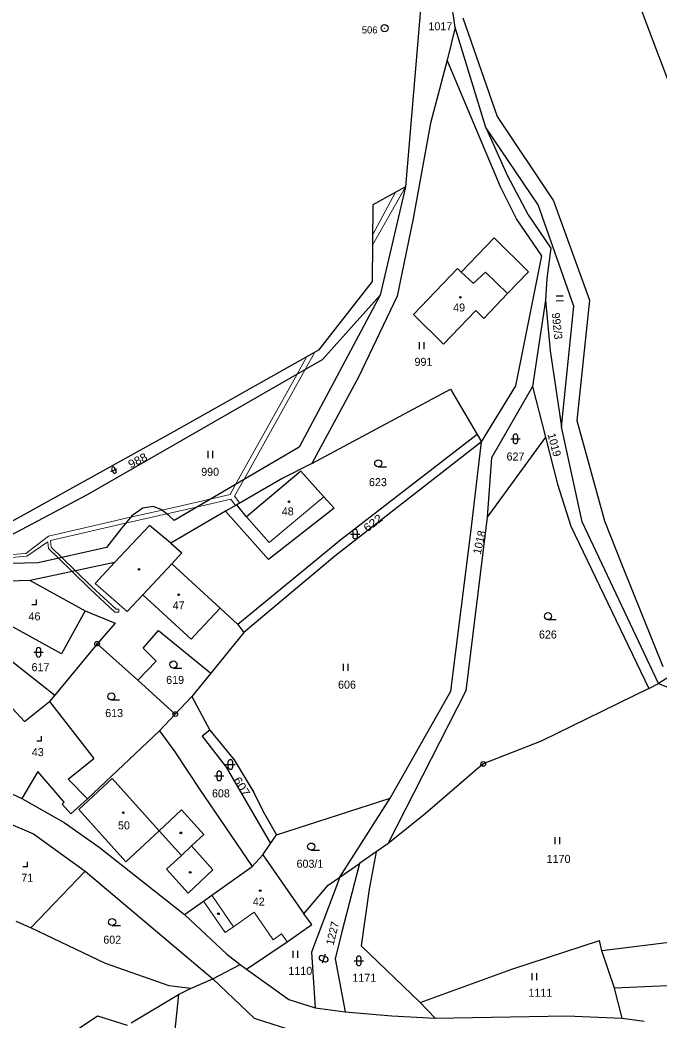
# Model space of a CAD drawing. Extents: x -744132 to -742433, y -984679 to -982287.
# Drawn here: x -742956.9 to -742821.1, y -983409.8 to -983197.5 of the extents above; entities that cross this region are included whole.
import ezdxf
from ezdxf.enums import TextEntityAlignment as Align

# ---------------------------------------------------------------- set-up
doc = ezdxf.new("R2010")
doc.units = 0
doc.header["$LTSCALE"] = 0.68
for name, color, linetype, lineweight in [('1', 7, 'Continuous', 25), ('13', 7, 'Continuous', 13), ('3', 7, 'Continuous', 25), ('4', 7, 'Continuous', 13), ('5', 7, 'Continuous', 25), ('8', 7, 'Continuous', 25)]:
    doc.layers.add(name, color=color, linetype=linetype, lineweight=lineweight)
doc.layers.add('2', color=7, linetype='Continuous')

msp = doc.modelspace()

# ---------------------------------------------------------------- linework, layer by layer
at = {"layer": '1'}
for p, q in [((-742864.59, -983199.1), (-742873.51, -983136.56)), ((-742821.79, -983203.81), (-742833.08, -983174.04)), ((-742871.62, -983191.87), (-742875.11, -983232.95)), ((-742862.92, -983197.05), (-742855.66, -983218)), ((-742864.59, -983199.1), (-742866.29, -983206.07)), ((-742858.03, -983220.3), (-742864.59, -983199.1)), ((-742797.61, -983268.25), (-742821.79, -983203.81)), ((-742866.29, -983206.07), (-742869.83, -983219.44)), ((-742854.97, -983232.92), (-742866.29, -983206.07)), ((-742855.66, -983218), (-742843.71, -983235.9)), ((-742869.83, -983219.44), (-742873.48, -983239.66)), ((-742858.03, -983220.3), (-742853.5, -983230.47)), ((-742846.95, -983236.77), (-742858.03, -983220.3)), ((-742853.5, -983230.47), (-742849.07, -983238.88)), ((-742875.11, -983232.95), (-742882.07, -983236.74)), ((-742875.11, -983232.95), (-742880.5, -983255.92)), ((-742851.57, -983239.74), (-742854.97, -983232.92)), ((-742882.07, -983236.74), (-742882.16, -983253.04)), ((-742839.35, -983258.24), (-742846.95, -983236.77)), ((-742843.71, -983235.9), (-742836.08, -983256.99)), ((-742873.48, -983239.66), (-742876.9, -983256.12)), ((-742846.16, -983247.57), (-742851.57, -983239.74)), ((-742849.07, -983238.88), (-742844.26, -983245.92)), ((-742856.29, -983243.76), (-742863.3, -983251.05)), ((-742856.29, -983243.76), (-742849.01, -983250.99)), ((-742844.26, -983245.92), (-742845.09, -983252.4)), ((-742851.67, -983275.18), (-742846.16, -983247.57)), ((-742864.08, -983250.28), (-742873.44, -983260.01)), ((-742864.08, -983250.28), (-742863.3, -983251.05)), ((-742849.01, -983250.99), (-742853.44, -983255.6)), ((-742845.09, -983252.4), (-742845.36, -983257.03)), ((-742882.16, -983253.04), (-742893.59, -983267.58)), ((-742880.5, -983255.92), (-742897.7, -983288.23)), ((-742892.71, -983269.57), (-742880.5, -983255.92)), ((-742876.9, -983256.12), (-742885.11, -983273.37)), ((-742853.44, -983255.6), (-742858.51, -983260.87)), ((-742845.36, -983257.03), (-742848.15, -983275.34)), ((-742845.36, -983257.03), (-742844.39, -983267.78)), ((-742842.01, -983283.87), (-742839.35, -983258.24)), ((-742836.08, -983256.99), (-742838.74, -983282.57)), ((-742873.44, -983260.01), (-742867.05, -983266.34)), ((-742860.19, -983259.21), (-742867.05, -983266.34)), ((-742860.19, -983259.21), (-742858.51, -983260.87)), ((-742893.59, -983267.58), (-742924.36, -983284.96)), ((-742844.39, -983267.78), (-742842.01, -983283.87)), ((-742942.64, -983298.23), (-742892.71, -983269.57)), ((-742885.11, -983273.37), (-742894.98, -983291.66)), ((-742858.98, -983287.1), (-742851.67, -983275.18)), ((-742848.15, -983275.34), (-742856.88, -983290.48)), ((-742848.15, -983275.34), (-742845.38, -983286.09)), ((-742894.98, -983291.66), (-742865.58, -983275.9)), ((-742865.58, -983275.9), (-742859.92, -983285.5)), ((-742837.63, -983304.08), (-742842.01, -983283.87)), ((-742838.74, -983282.57), (-742832.89, -983303.86)), ((-742924.36, -983284.96), (-742960.76, -983305.09)), ((-742859.92, -983285.5), (-742888.87, -983307.86)), ((-742859.92, -983285.5), (-742858.98, -983287.1)), ((-742845.38, -983286.09), (-742857.78, -983303.07)), ((-742845.38, -983286.09), (-742842.85, -983296.05)), ((-742897.7, -983288.23), (-742924.23, -983303.81)), ((-742858.98, -983287.1), (-742890.09, -983311.32)), ((-742861.15, -983305.74), (-742858.98, -983287.1)), ((-742856.88, -983290.48), (-742857.78, -983303.07)), ((-742894.98, -983291.66), (-742901.13, -983294.8)), ((-742901.13, -983294.8), (-742910.94, -983300.44)), ((-742897.3, -983293.29), (-742908.85, -983302.98)), ((-742892.44, -983298.74), (-742897.3, -983293.29)), ((-742842.85, -983296.05), (-742840, -983304.98)), ((-742960.13, -983307.51), (-742942.64, -983298.23)), ((-742892.44, -983298.74), (-742890.26, -983301.17)), ((-742930.9, -983301.18), (-742933.21, -983302.8)), ((-742928.67, -983300.8), (-742930.9, -983301.18)), ((-742926.98, -983301.41), (-742928.67, -983300.8)), ((-742910.94, -983300.44), (-742913.34, -983301.82)), ((-742908.85, -983302.98), (-742910.94, -983300.44)), ((-742890.26, -983301.17), (-742904.17, -983312.03)), ((-742933.21, -983302.8), (-742935.36, -983305.34)), ((-742925.36, -983302.72), (-742926.98, -983301.41)), ((-742924.23, -983303.81), (-742925.36, -983302.72)), ((-742913.34, -983301.82), (-742924.89, -983308.61)), ((-742904.17, -983312.03), (-742913.34, -983301.82)), ((-742857.78, -983303.07), (-742862.33, -983339.94)), ((-742935.36, -983305.34), (-742938.6, -983309.49)), ((-742929.46, -983304.83), (-742936.87, -983312.72)), ((-742924.89, -983308.61), (-742929.46, -983304.83)), ((-742840, -983304.98), (-742823.44, -983339.47)), ((-742821.43, -983338.41), (-742837.63, -983304.08)), ((-742832.89, -983303.86), (-742829.22, -983312.97)), ((-742938.6, -983309.49), (-742953.06, -983312.8)), ((-742924.89, -983308.61), (-742922.56, -983310.67)), ((-742888.87, -983307.86), (-742910.72, -983325.83)), ((-742924.74, -983313), (-742922.56, -983310.67)), ((-742890.09, -983311.32), (-742909.44, -983327.53)), ((-742953.06, -983312.8), (-742967.82, -983313.13)), ((-742936.87, -983312.72), (-742954.79, -983316.51)), ((-742924.74, -983313), (-742914.45, -983322.42)), ((-742829.22, -983312.97), (-742820.49, -983334.77)), ((-742954.79, -983316.51), (-742965.92, -983316.88)), ((-742954.79, -983316.51), (-742943.08, -983322.99)), ((-742948.13, -983332.12), (-742967.49, -983321.4)), ((-742914.45, -983322.42), (-742910.72, -983325.83)), ((-742970.08, -983324.65), (-742949.55, -983340.86)), ((-742943.08, -983322.99), (-742948.13, -983332.12)), ((-742943.08, -983322.99), (-742936.73, -983325.56)), ((-742936.73, -983325.56), (-742940.59, -983329.95)), ((-742910.72, -983325.83), (-742909.44, -983327.53)), ((-742930.81, -983330.88), (-742927.51, -983327.15)), ((-742927.51, -983327.15), (-742916.46, -983336.18)), ((-742909.44, -983327.53), (-742916.46, -983336.18)), ((-742803.4, -983327.24), (-742821.43, -983338.41)), ((-742940.59, -983329.95), (-742949.55, -983340.86)), ((-742940.59, -983329.95), (-742931.96, -983337.71)), ((-742928.07, -983333.63), (-742930.81, -983330.88)), ((-742931.96, -983337.71), (-742928.07, -983333.63)), ((-742916.46, -983336.18), (-742920.49, -983341.17)), ((-742931.96, -983337.71), (-742923.98, -983344.89)), ((-742823.44, -983339.47), (-742846.3, -983350.66)), ((-742823.44, -983339.47), (-742821.43, -983338.41)), ((-742821.43, -983338.41), (-742812.22, -983342.05)), ((-742949.55, -983340.86), (-742950.68, -983342.24)), ((-742920.49, -983341.17), (-742923.98, -983344.89)), ((-742920.49, -983341.17), (-742916.66, -983348.29)), ((-742862.33, -983339.94), (-742878.89, -983372.41)), ((-742958.59, -983343.6), (-742956, -983346.48)), ((-742956, -983346.48), (-742950.68, -983342.24)), ((-742950.68, -983342.24), (-742941.24, -983354.34)), ((-742923.98, -983344.89), (-742927.32, -983348.45)), ((-742942.59, -983362.9), (-742927.32, -983348.45)), ((-742927.32, -983348.45), (-742924.09, -983352.87)), ((-742916.66, -983348.29), (-742918.3, -983349.55)), ((-742918.3, -983349.55), (-742913.15, -983356.14)), ((-742916.66, -983348.29), (-742911.47, -983354.57)), ((-742846.3, -983350.66), (-742858.61, -983355.47)), ((-742946.69, -983358.69), (-742941.24, -983354.34)), ((-742924.09, -983352.87), (-742918.82, -983360.84)), ((-742913.15, -983356.14), (-742903.77, -983372.37)), ((-742911.47, -983354.57), (-742907.28, -983361.55)), ((-742858.61, -983355.47), (-742870.9, -983366.07)), ((-742953.17, -983357.07), (-742956.57, -983362.81)), ((-742947.56, -983363.6), (-742953.17, -983357.07)), ((-742965.59, -983358.65), (-742956.57, -983362.81)), ((-742942.59, -983362.9), (-742946.69, -983358.69)), ((-742956.57, -983362.81), (-742947.56, -983367.89)), ((-742918.82, -983360.84), (-742907.69, -983377.24)), ((-742907.28, -983361.55), (-742905.29, -983365.58)), ((-742902.51, -983370.5), (-742878.36, -983362.71)), ((-742889.06, -983379.52), (-742878.36, -983362.71)), ((-742947.96, -983363.98), (-742947.56, -983363.6)), ((-742946.12, -983366.09), (-742947.96, -983363.98)), ((-742942.59, -983362.9), (-742946.12, -983366.09)), ((-742905.29, -983365.58), (-742902.51, -983370.5)), ((-742870.9, -983366.07), (-742878.89, -983372.41)), ((-742959.86, -983367.82), (-742954.09, -983370.28)), ((-742947.56, -983367.89), (-742940.17, -983373.17)), ((-742954.09, -983370.28), (-742943.11, -983378.21)), ((-742903.77, -983372.37), (-742902.51, -983370.5)), ((-742940.17, -983373.17), (-742922.02, -983387.45)), ((-742905.39, -983374.79), (-742903.77, -983372.37)), ((-742878.89, -983372.41), (-742881.35, -983374.12)), ((-742907.69, -983377.24), (-742905.39, -983374.79)), ((-742905.39, -983374.79), (-742896.68, -983387.29)), ((-742881.35, -983374.12), (-742884.9, -983376.61)), ((-742881.35, -983374.12), (-742882.84, -983382.05)), ((-742916.22, -983383.33), (-742907.69, -983377.24)), ((-742889.06, -983379.52), (-742884.9, -983376.61)), ((-742884.9, -983376.61), (-742888.71, -983391.39)), ((-742954.64, -983390.28), (-742943.11, -983378.21)), ((-742943.11, -983378.21), (-742916.02, -983401.08)), ((-742889.06, -983379.52), (-742895.08, -983395.46)), ((-742891.5, -983381.21), (-742889.06, -983379.52)), ((-742896.68, -983387.29), (-742891.5, -983381.21)), ((-742917.99, -983384.59), (-742916.22, -983383.33)), ((-742882.84, -983382.05), (-742884.51, -983394.08)), ((-742922.02, -983387.45), (-742917.99, -983384.59)), ((-742895.02, -983389.59), (-742896.68, -983387.29)), ((-742954.64, -983390.28), (-742957.77, -983388.91)), ((-742938.76, -983397.82), (-742954.64, -983390.28)), ((-742900.25, -983393.27), (-742895.02, -983389.59)), ((-742888.71, -983391.39), (-742890.03, -983396.82)), ((-742805.83, -983391.74), (-742833.43, -983395.18)), ((-742908.85, -983399.04), (-742900.25, -983393.27)), ((-742884.51, -983394.08), (-742871.99, -983406.12)), ((-742852.52, -983399.07), (-742833.91, -983392.97)), ((-742833.43, -983395.18), (-742833.91, -983392.97)), ((-742913.04, -983395.87), (-742910.19, -983398.02)), ((-742895.08, -983395.46), (-742894.3, -983407.24)), ((-742890.03, -983396.82), (-742887.92, -983408.09)), ((-742830.73, -983403.05), (-742833.43, -983395.18)), ((-742925.29, -983402.56), (-742938.76, -983397.82)), ((-742916.02, -983401.08), (-742910.19, -983398.02)), ((-742910.19, -983398.02), (-742908.85, -983399.04)), ((-742920.73, -983403.13), (-742916.02, -983401.08)), ((-742916.02, -983401.08), (-742907.2, -983409.42)), ((-742908.85, -983399.04), (-742899.87, -983405.48)), ((-742871.99, -983406.12), (-742852.52, -983399.07)), ((-742920.73, -983403.13), (-742925.29, -983402.56)), ((-742923.27, -983404.41), (-742920.73, -983403.13)), ((-742800.93, -983401.85), (-742830.73, -983403.05)), ((-742829.1, -983409.43), (-742830.73, -983403.05)), ((-742933.33, -983410.46), (-742923.27, -983404.41)), ((-742923.27, -983404.41), (-742925.2, -983422.45)), ((-742899.87, -983405.48), (-742894.3, -983407.24)), ((-742894.3, -983407.24), (-742887.92, -983408.09)), ((-742871.99, -983406.12), (-742868.78, -983409.43)), ((-742907.2, -983409.42), (-742894.67, -983413.5)), ((-742887.92, -983408.09), (-742877.99, -983408.97)), ((-742877.99, -983408.97), (-742868.78, -983409.43)), ((-742868.78, -983409.43), (-742840.88, -983408.98)), ((-742840.88, -983408.98), (-742829.1, -983409.43)), ((-742829.1, -983409.43), (-742824.43, -983410.09))]:
    msp.add_line(p, q, dxfattribs=at)
for points in [[(-742878.36, -983362.71), (-742865.49, -983340.04), (-742861.15, -983305.74)], [(-742922.02, -983387.45), (-742921.94, -983387.51), (-742913.04, -983395.87)], [(-742954.34, -983418.3), (-742940.5, -983408.97), (-742934.16, -983410.91)]]:
    msp.add_lwpolyline(points, dxfattribs=at)
at = {"layer": '13'}
for points in [[(-742877.21, -983234.09), (-742882.11, -983243.17), (-742882.12, -983245.29), (-742875.11, -983232.95)], [(-742896.44, -983271.71), (-742894.39, -983268.03), (-742896.06, -983268.98), (-742898.12, -983272.68)], [(-742945.87, -983314.62), (-742942.18, -983318.21), (-742936.8, -983323.23), (-742935.94, -983323.21), (-742935.96, -983322.61), (-742936.56, -983322.63), (-742941.76, -983317.77), (-742945.15, -983314.47)]]:
    msp.add_lwpolyline(points, close=True, dxfattribs=at)
msp.add_lwpolyline([(-742959.6, -983311.7), (-742955.5, -983311.37), (-742951.01, -983308.3), (-742950.88, -983309.74), (-742948.75, -983311.81), (-742945.87, -983314.62), (-742945.15, -983314.47), (-742948.05, -983311.65), (-742950.3, -983309.46), (-742950.44, -983308.01), (-742934.54, -983304.37), (-742925.8, -983302.36), (-742919.19, -983300.85), (-742912.21, -983299.25), (-742911.17, -983300.57), (-742910.3, -983300.07), (-742911.41, -983298.64), (-742909.46, -983295.14), (-742896.44, -983271.71), (-742898.12, -983272.68), (-742911.17, -983296.14), (-742912.34, -983298.25), (-742916.31, -983299.16), (-742926.79, -983301.56), (-742933.46, -983303.09), (-742950.89, -983307.09), (-742955.72, -983310.79), (-742959.6, -983311.1)], dxfattribs=at)
at = {"layer": '3'}
for p, q in [((-742843.109, -983256.109), (-742841.609, -983256.083)), ((-742843.091, -983257.11), (-742841.592, -983257.084)), ((-742872.131, -983267.38), (-742872.131, -983265.88)), ((-742871.13, -983267.38), (-742871.13, -983265.88)), ((-742852.761, -983286.441), (-742850.759, -983286.441)), ((-742852.261, -983285.941), (-742852.261, -983286.942)), ((-742851.259, -983286.942), (-742851.259, -983285.941)), ((-742917.021, -983290.52), (-742917.021, -983289.02)), ((-742916.02, -983290.52), (-742916.02, -983289.02)), ((-742937.635, -983293.396), (-742936.354, -983292.826)), ((-742936.532, -983293.289), (-742936.817, -983292.649)), ((-742880.893, -983292.38), (-742879.143, -983292.38)), ((-742937.457, -983292.934), (-742937.172, -983293.574)), ((-742886.801, -983306.671), (-742884.799, -983306.671)), ((-742886.301, -983306.171), (-742886.301, -983307.172)), ((-742885.299, -983307.172), (-742885.299, -983306.171)), ((-742844.863, -983324.83), (-742843.113, -983324.83)), ((-742954.011, -983331.761), (-742952.009, -983331.761)), ((-742953.511, -983331.261), (-742953.511, -983332.262)), ((-742952.509, -983332.262), (-742952.509, -983331.261)), ((-742924.373, -983335.11), (-742922.623, -983335.11)), ((-742888.261, -983335.7), (-742888.261, -983334.2)), ((-742887.26, -983335.7), (-742887.26, -983334.2)), ((-742937.543, -983341.88), (-742935.793, -983341.88)), ((-742913.291, -983355.581), (-742911.289, -983355.581)), ((-742912.791, -983355.081), (-742912.791, -983356.082)), ((-742911.789, -983356.082), (-742911.789, -983355.081)), ((-742915.641, -983357.991), (-742913.639, -983357.991)), ((-742915.141, -983357.491), (-742915.141, -983358.492)), ((-742914.139, -983358.492), (-742914.139, -983357.491)), ((-742843.361, -983372.53), (-742843.361, -983371.03)), ((-742842.36, -983372.53), (-742842.36, -983371.03)), ((-742895.133, -983373.76), (-742893.383, -983373.76)), ((-742937.383, -983389.79), (-742935.633, -983389.79)), ((-742898.951, -983396.62), (-742898.951, -983395.12)), ((-742897.95, -983396.62), (-742897.95, -983395.12)), ((-742892.16, -983395.879), (-742892.812, -983397.772)), ((-742891.849, -983396.515), (-742892.796, -983396.189)), ((-742885.531, -983396.771), (-742885.531, -983397.772)), ((-742884.529, -983397.772), (-742884.529, -983396.771)), ((-742893.122, -983397.136), (-742892.175, -983397.461)), ((-742886.031, -983397.271), (-742884.029, -983397.271)), ((-742848.241, -983401.41), (-742848.241, -983399.91)), ((-742847.24, -983401.41), (-742847.24, -983399.91))]:
    msp.add_line(p, q, dxfattribs=at)
for points in [[(-742954.441, -983321.58), (-742953.44, -983321.58), (-742953.44, -983320.58)], [(-742953.401, -983350.59), (-742952.4, -983350.59), (-742952.4, -983349.59)], [(-742956.321, -983377.22), (-742955.32, -983377.22), (-742955.32, -983376.22)]]:
    msp.add_lwpolyline(points, dxfattribs=at)
for centre in [(-742880.8929, -983291.6298), (-742844.8629, -983324.0798), (-742924.3729, -983334.3598), (-742937.5429, -983341.1298), (-742895.1329, -983373.0098), (-742937.3829, -983389.0398)]:
    msp.add_circle(centre, 0.75, dxfattribs=at)
for centre, radius, start, end in [((-742851.76, -983285.9409), 0.5, 0, 180), ((-742851.76, -983286.9409), 0.5, 180, 359.98789), ((-742937.1368, -983292.7914), 0.35, 24, 204), ((-742936.8521, -983293.4308), 0.35, 204, 23.98789), ((-742885.8, -983306.1709), 0.5, 0, 180), ((-742885.8, -983307.1709), 0.5, 180, 359.98789), ((-742953.01, -983331.2609), 0.5, 0, 180), ((-742953.01, -983332.2609), 0.5, 180, 359.98789), ((-742912.29, -983355.0809), 0.5, 0, 180), ((-742912.29, -983356.0809), 0.5, 180, 359.98789), ((-742914.64, -983357.4909), 0.5, 0, 180), ((-742914.64, -983358.4909), 0.5, 180, 359.98789), ((-742892.9581, -983396.6625), 0.5, 71, 250.98789), ((-742892.0126, -983396.9881), 0.5, 251, 71), ((-742885.03, -983396.7709), 0.5, 0, 180), ((-742885.03, -983397.7709), 0.5, 180, 359.98789)]:
    msp.add_arc(centre, radius, start, end, dxfattribs=at)
at = {"layer": '4'}
for p, q in [((-742863.3, -983251.05), (-742860.82, -983253.33)), ((-742858.13, -983251.02), (-742860.71, -983253.44)), ((-742858.13, -983251.02), (-742853.44, -983255.6)), ((-742860.82, -983253.33), (-742860.71, -983253.44)), ((-742904.06, -983308.46), (-742892.44, -983298.74)), ((-742908.85, -983302.98), (-742904.06, -983308.46)), ((-742936.87, -983312.72), (-742941, -983317.12)), ((-742930.89, -983319.55), (-742924.74, -983313)), ((-742941, -983317.12), (-742934.22, -983323.1)), ((-742934.22, -983323.1), (-742930.89, -983319.55)), ((-742930.89, -983319.55), (-742920.61, -983328.96)), ((-742918.84, -983327.08), (-742914.45, -983322.42)), ((-742920.61, -983328.96), (-742918.84, -983327.08)), ((-742944.48, -983365.13), (-742937.41, -983358.58)), ((-742937.41, -983358.58), (-742927.42, -983369.67)), ((-742944.48, -983365.13), (-742934.49, -983376.22)), ((-742927.42, -983369.67), (-742922.63, -983365.22)), ((-742922.63, -983365.22), (-742917.92, -983370.45)), ((-742934.49, -983376.22), (-742927.42, -983369.67)), ((-742927.42, -983369.67), (-742922.69, -983374.92)), ((-742920.52, -983372.89), (-742917.92, -983370.45)), ((-742922.69, -983374.92), (-742920.52, -983372.89)), ((-742920.52, -983372.89), (-742915.98, -983377.93)), ((-742925.81, -983377.84), (-742922.69, -983374.92)), ((-742925.81, -983377.84), (-742921.27, -983382.88)), ((-742921.27, -983382.88), (-742915.98, -983377.93)), ((-742916.22, -983383.33), (-742911.59, -983390.02)), ((-742917.99, -983384.59), (-742913.36, -983391.27)), ((-742911.59, -983390.02), (-742907.23, -983386.93)), ((-742907.23, -983386.93), (-742903.18, -983392.78)), ((-742913.36, -983391.27), (-742911.59, -983390.02)), ((-742903.18, -983392.78), (-742901.45, -983391.55)), ((-742901.45, -983391.55), (-742900.25, -983393.27))]:
    msp.add_line(p, q, dxfattribs=at)
at = {"layer": '5'}
for centre in [(-742863.4568, -983256.3892), (-742899.8468, -983299.7892), (-742931.6868, -983314.1592), (-742923.2468, -983319.5592), (-742935.0068, -983365.8292), (-742922.7868, -983370.0992), (-742920.8068, -983378.4692), (-742905.9568, -983382.3892), (-742914.8168, -983387.2892)]:
    msp.add_circle(centre, 0.175, dxfattribs=at)
at = {"layer": '8'}
for centre, radius in [((-742879.54, -983199.2498), 0.75), ((-742879.54, -983199.2498), 0.03), ((-742940.59, -983329.9499), 0.5), ((-742940.59, -983329.9499), 0.0303), ((-742923.98, -983344.8899), 0.5), ((-742923.98, -983344.8899), 0.0303), ((-742858.61, -983355.4699), 0.5), ((-742858.61, -983355.4699), 0.0303)]:
    msp.add_circle(centre, radius, dxfattribs=at)

# ---------------------------------------------------------------- texts
at = {"layer": '2'}
for s, p in [('1017', (-742870.24, -983199.695)), ('49', (-742864.99, -983259.395)), ('991', (-742873.19, -983270.935)), ('627', (-742853.65, -983291.045)), ('990', (-742918.48, -983294.285)), ('623', (-742882.86, -983296.485)), ('48', (-742901.37, -983302.685)), ('47', (-742924.53, -983322.645)), ('46', (-742955.13, -983324.975)), ('626', (-742846.78, -983328.835)), ('617', (-742954.49, -983335.775)), ('619', (-742925.91, -983338.475)), ('606', (-742889.43, -983339.485)), ('613', (-742938.86, -983345.515)), ('43', (-742954.44, -983353.815)), ('608', (-742916.19, -983362.555)), ('50', (-742936.14, -983369.355)), ('1170', (-742845.14, -983376.475)), ('603/1', (-742898.24, -983377.505)), ('71', (-742956.66, -983380.495)), ('42', (-742907.52, -983385.545)), ('602', (-742939.26, -983393.635)), ('1110', (-742899.96, -983400.245)), ('1171', (-742886.39, -983401.715)), ('1111', (-742849, -983404.905))]:
    msp.add_text(s, height=1.7, dxfattribs=at).set_placement(p)
for s, rotation, p in [('992/3', 276, (-742844.062, -983259.754)), ('1019', 285, (-742844.98, -983285.489)), ('1018', 77, (-742859.165, -983311.075)), ('1227', 76, (-742890.397, -983394.082))]:
    msp.add_text(s, height=1.7, rotation=rotation, dxfattribs=at).set_placement(p)
for s, rotation, width, p in [('988', 27, 1.1, (-742933.437, -983292.738)), ('622', 38, 1.15, (-742883.208, -983306.314)), ('607', 302, 1.15, (-742911.72, -983358.875))]:
    msp.add_text(s, height=1.7, rotation=rotation, dxfattribs=dict(at, width=width)).set_placement(p)
at = {"layer": '8'}
msp.add_text('506', height=1.5, dxfattribs=at).set_placement((-742881.039, -983200.367), align=Align.RIGHT)

doc.saveas('drawing.dxf')
